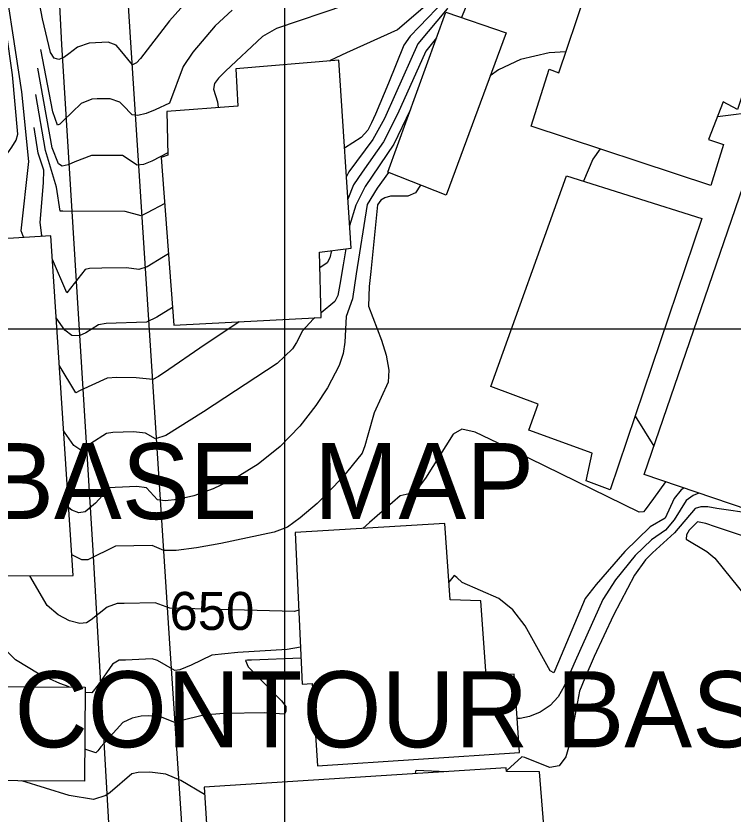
# Model space of a CAD drawing. Extents: x 79600 to 91800, y 75600 to 84400.
# Drawn here: x 85858.7 to 86236.1, y 82744.9 to 83164.7 of the extents above; entities that cross this region are included whole.
import ezdxf

# ---------------------------------------------------------------- set-up
doc = ezdxf.new("R2010")
doc.units = 0
for name, color, linetype in [('084-085$0$TI_ORTHO_BM', 7, 'Continuous'), ('084-085$0$TI_ORTHO_CBM', 7, 'Continuous'), ('084-090$0$BLDG', 7, 'Continuous'), ('084-090$0$GRID', 7, 'Continuous'), ('084-090$0$INDEX', 7, 'Continuous'), ('084-090$0$INDXLBL', 7, 'Continuous'), ('084-090$0$INTER', 7, 'Continuous'), ('084-090$0$ROAD', 7, 'Continuous')]:
    doc.layers.add(name, color=color, linetype=linetype)

msp = doc.modelspace()

# ---------------------------------------------------------------- linework, layer by layer
at = {"layer": '084-090$0$BLDG'}
for points in [[(86224.34, 83075.53), (86129.86, 83106.71), (86139.29, 83136.6), (86144.4, 83134.8), (86185.95, 83257.94), (86257.98, 83232.87), (86252.75, 83215.38), (86269.8, 83209.06), (86238.46, 83115.5), (86230.85, 83119.44), (86223.17, 83099.76), (86231.07, 83097.06)], [(86271.35, 82895.67), (86189.25, 82923.42), (86271.34, 83162.45), (86259.26, 83166.5), (86274.11, 83210.03), (86365.03, 83179.9)], [(86054.44, 83082.5), (86084.95, 83166.63), (86116.71, 83155.83), (86085.13, 83070.45)], [(85935.18, 83090.27), (85941.77, 83002.03), (86019.38, 83006.04), (86018.43, 83040.46), (86035.08, 83042.47), (86028.7, 83141.37), (85974.4, 83136.82), (85975.52, 83117.23), (85938.19, 83114.39), (85938.72, 83091.39)], [(86148.49, 83080.49), (86219.57, 83058.19), (86171.42, 82915.37), (86158.87, 82920.19), (86161.97, 82934.73), (86128.66, 82946.75), (86133.46, 82960.54), (86108.67, 82969.71)], [(85888.88, 82870.28), (85877.08, 83048.94), (85834.65, 83046.36), (85835.88, 82984.31), (85811.03, 82983.75), (85811.47, 82970.17), (85802.36, 82970.08), (85801.56, 82988.45), (85761.59, 82987.28), (85735.2, 83001.22), (85667.5, 82869.48)], [(86087.24, 82857.57), (86084.37, 82897.68), (86005.68, 82893.05), (86009.4, 82813.26), (86014.65, 82813.47), (86017.39, 82770.27), (86123.69, 82777.19), (86120.97, 82818.38), (86106.16, 82817.62), (86103.3, 82857.11)], [(85895.12, 82811.7), (85894.84, 82762.15), (85719.62, 82763.12), (85719.9, 82812.68)], [(85957.75, 82759.03), (85963.05, 82676.17), (86070.75, 82682.95), (86071.39, 82680.02), (86081.89, 82679.66), (86084.04, 82650.04), (86099.94, 82650.05), (86098.36, 82685.23), (86122.28, 82686.39), (86120.57, 82718.03), (86138.16, 82719.12), (86134.29, 82767.1), (86116.85, 82767.24), (86116.67, 82769.24)]]:
    msp.add_lwpolyline(points, close=True, dxfattribs=at)
at = {"layer": '084-090$0$GRID'}
for p, q in [((86000, 84000), (86000, 80000)), ((90000, 83000), (85000, 83000))]:
    msp.add_line(p, q, dxfattribs=at)
at = {"layer": '084-090$0$INDEX'}
msp.add_line((86184.51, 82954.18), (86194.39, 82938.38), dxfattribs=at)
for points in [[(85862.91, 83048.08), (85862.45, 83048.8), (85861.47, 83051.63), (85865.56, 83088.04), (85861.91, 83124.82), (85850.49, 83199.61), (85847.19, 83227.14), (85846.11, 83237.85), (85846.13, 83243.79), (85847.29, 83252.3), (85853.54, 83269.76), (85855.43, 83279.06), (85857.03, 83295.86)], [(86185.74, 83257.33), (86179.65, 83255.74), (86135.32, 83250.43), (86131.34, 83249.64), (86125.16, 83241.02), (86118.72, 83230.33), (86112.78, 83216.12), (86097.23, 83191.67), (86085.56, 83168.46), (86070.22, 83150.05), (86058.41, 83123.76), (86052.69, 83110.68), (86046.58, 83099.69), (86033.94, 83082.63), (86032.64, 83080.28)], [(85960.63, 83185.74), (85939.62, 83162.11), (85924.25, 83142.28), (85922.22, 83139.93), (85919.98, 83139.02), (85913.59, 83146.89), (85911.46, 83149.25), (85907.28, 83150.94), (85897.34, 83150.36), (85891.16, 83148.3), (85886.62, 83144.69), (85883.99, 83142.82), (85881.24, 83141.79), (85878.78, 83142.48), (85876.89, 83145.53), (85872.72, 83163.17), (85869.32, 83180.76)], [(86255.19, 83115.42), (86250.25, 83114.38), (86227.82, 83111.66)], [(86166.23, 83094.7), (86162.37, 83089.3), (86157.35, 83077.71)], [(85941.07, 83011.37), (85932.84, 83006.31), (85927.38, 83003.69), (85906.16, 83002.84), (85902.24, 83002.28), (85895.54, 82998), (85891.94, 82996.43), (85888.09, 82996.63), (85884.41, 82999.44), (85879.92, 83005.83)], [(86200.61, 82919.58), (86194.17, 82910.89), (86189.77, 82904.85), (86188.96, 82903.81), (86186.65, 82903.74), (86112.5, 82939.93), (86100.31, 82945.77), (86093.41, 82947.4), (86088.76, 82944.7), (86074.21, 82921.59), (86070.38, 82916.41), (86067.3, 82913.67), (86060.94, 82912.33), (86044.78, 82898.2), (86041.28, 82895.14)], [(86007.59, 82852.07), (86005.28, 82851.38), (85939.75, 82853.14), (85931.93, 82855.9), (85915.6, 82855.58), (85911.91, 82855.65), (85906.77, 82853.61), (85898.25, 82847.08), (85895.82, 82845.5), (85892.28, 82845.15), (85887, 82846.54), (85880.9, 82849.7), (85875.25, 82854.58), (85865.96, 82870.19)]]:
    msp.add_lwpolyline(points, dxfattribs=at)
at = {"layer": '084-090$0$INTER'}
for points in [[(85849.74, 83047.28), (85847.28, 83049.36), (85845.44, 83053.99), (85845.41, 83061.35), (85848.18, 83077.64), (85850.17, 83086.18), (85854.05, 83092.16), (85856.49, 83095.57), (85858.81, 83099.26), (85859.7, 83102.5), (85857, 83133.68), (85847.05, 83201.84), (85842.59, 83233.97), (85842.03, 83240.38), (85842.77, 83250.25), (85844.07, 83257.24), (85847.23, 83264.53), (85853.51, 83286.9), (85856.07, 83298.42)], [(86160.92, 83183.76), (86157.37, 83184.19), (86141.69, 83187.17), (86131.3, 83190.7), (86121.5, 83197.06), (86118.5, 83198.76), (86114.24, 83199.67), (86112.05, 83198.53), (86101.29, 83183.81), (86093.21, 83163.82)], [(86083.14, 83177.8), (86067.98, 83164.55), (86059.47, 83157.4), (86032.69, 83145.19), (86024.04, 83141.2), (86023.81, 83140.96)], [(86084.35, 83173.13), (86070.83, 83158.9), (86066.1, 83153.96), (86062.92, 83149.34), (86054.75, 83129.33), (86047.87, 83112.96), (86045.9, 83108.41), (86043.87, 83104.53), (86040.37, 83100.74), (86031.68, 83095.17)], [(85972.44, 83167.64), (85963.5, 83159.46), (85951.74, 83145.65), (85946.66, 83138.12), (85939.55, 83118.79), (85931.96, 83115.21), (85927.26, 83113.41), (85922.93, 83112.38), (85919.84, 83112.69), (85914.99, 83117.74), (85913.4, 83119.34), (85908.23, 83121.02), (85901.49, 83121.04), (85898.62, 83120.85), (85893.1, 83118.58), (85883.66, 83109.46), (85881.77, 83107.67), (85880.61, 83107.21), (85878.19, 83114.29), (85871.83, 83146.94)], [(86032.11, 83170.31), (85995.8, 83158.02), (85988.54, 83153.84), (85969.06, 83135.69), (85965.31, 83131.99), (85963.26, 83129.21), (85962.66, 83126.11), (85964.85, 83119.48), (85965.08, 83116.43)], [(86080.05, 83153.12), (86074.35, 83146.14), (86059.58, 83113.09), (86052.09, 83098.42), (86041, 83082.57), (86036.31, 83075.8), (86033.41, 83068.29)], [(86148.12, 83145.82), (86139.32, 83145.35), (86124.29, 83141.77), (86112.71, 83136.34), (86108.31, 83133.1)], [(85938.69, 83092.71), (85930.29, 83088.32), (85925.81, 83086.55), (85922.54, 83086.26), (85914.77, 83091.35), (85898.48, 83091.19), (85889.65, 83087.97), (85886.18, 83086.31), (85883.11, 83085.73), (85881.12, 83086.89), (85877.88, 83095.3), (85870.31, 83137.21)], [(85937, 83065.97), (85927.87, 83061.15), (85924.58, 83059.51), (85916.22, 83061.79), (85883.32, 83061.95), (85881.99, 83061.93), (85880.1, 83074.56), (85874.23, 83093.83), (85869.22, 83123.37)], [(86066.26, 83115.08), (86057.6, 83097.16), (86042.52, 83074.92), (86037.64, 83065.08), (86034.32, 83054.23)], [(85872.64, 83048.67), (85872.37, 83049.27), (85871.53, 83056.04), (85873.32, 83076.91), (85873.48, 83083.56), (85870.46, 83092.52), (85868.33, 83105.97)], [(86054.75, 83082.38), (86048.74, 83074.04), (86043.61, 83065.54), (86037.73, 83029.11), (86035.81, 83015.95), (86032.46, 83006.61), (86031.86, 82993.01), (86030.92, 82987.1), (86028.78, 82980.77), (86022.72, 82969.14), (86016.48, 82959.7), (86008.06, 82948.86), (85997.84, 82938.17), (85986.28, 82928.93), (85974.22, 82921.49), (85962.6, 82915.92), (85952.28, 82912.24), (85943.72, 82910.25), (85937.3, 82909.65), (85933.22, 82910.15), (85927.49, 82916.44), (85922.42, 82917.11), (85911.03, 82916.67), (85907.97, 82916.46), (85900.6, 82908.44), (85895.1, 82903.88), (85891.74, 82903.28), (85888.09, 82904.69), (85886.52, 82905.95)], [(86071.69, 83075.72), (86069.02, 83071.61), (86064.88, 83069.83), (86055.86, 83069.81), (86052.77, 83069.06), (86050.8, 83067.71), (86049.02, 83065.28), (86045.49, 83030.25), (86044.63, 83022.31), (86044.32, 83012.08), (86051.09, 82994.18), (86053.52, 82986.18), (86054.89, 82978.37), (86054.61, 82971.96), (86047.29, 82955.98), (86043.83, 82944.08), (86042.26, 82938.47), (86040.99, 82934.76), (86030.36, 82921.8), (86017.2, 82908.21), (86008.3, 82900.66), (86001.67, 82895.78), (85994.61, 82893.09), (85966.55, 82887.11), (85953.69, 82884.9), (85942.99, 82883.52), (85936.5, 82883.42), (85930.49, 82886.19), (85911.13, 82885.78), (85896.63, 82878.63), (85893.32, 82878.51), (85888.16, 82881.21)], [(86032.34, 83042.14), (86030.98, 83033.68), (86029.15, 83023.45), (86028.11, 83017.71), (86026.54, 83014.4), (86019.31, 83008.58)], [(85938.97, 83039.48), (85936.31, 83037.93), (85927.74, 83032.75), (85923.4, 83031.31), (85916.91, 83032.26), (85903.88, 83031.98), (85897.48, 83031.9), (85895.21, 83031.37), (85885.46, 83019), (85877.89, 83036.64)], [(86024.84, 83041.23), (86023.87, 83037.39), (86022.48, 83034.74), (86018.66, 83032.19)], [(85976.18, 83003.81), (85955.42, 82989.93), (85939.19, 82978.68), (85933.78, 82975.09), (85930.7, 82973.43), (85922.07, 82974.36), (85911.87, 82974.51), (85906.78, 82974.11), (85892.6, 82967.64), (85890.31, 82966.39), (85881.56, 82981.05)], [(86015.94, 83005.86), (86015.15, 83005.22), (86009.46, 82999.05), (86006.31, 82992.86), (86004.31, 82989.6), (85996.26, 82981.88), (85957.36, 82956.45), (85937.54, 82943.93), (85932.21, 82942.18), (85926.89, 82945.21), (85920.63, 82945.85), (85909.71, 82945.49), (85906.43, 82945.04), (85898.18, 82939.85), (85895.72, 82937.38), (85892.87, 82936.3), (85889.14, 82938.7), (85884.3, 82945.82), (85883.82, 82946.81)], [(86210.1, 82916.37), (86208.79, 82915.39), (86205.03, 82910.78), (86200.43, 82900.5), (86192.41, 82895.9), (86179.08, 82883.01), (86164.08, 82865.61), (86158.3, 82858.22), (86144.16, 82824.88), (86141.78, 82819.18), (86139.89, 82820.2), (86126.68, 82843.79), (86120.13, 82852.25), (86112.89, 82858.3), (86093.62, 82866.75), (86090.68, 82869.34), (86089.26, 82870.29), (86086.58, 82866.78)], [(86217.99, 82913.71), (86215.15, 82912.44), (86211.46, 82909.74), (86205.03, 82899.69), (86200.46, 82894.15), (86193.09, 82889.08), (86184.59, 82880.82), (86174.19, 82868.06), (86167.63, 82857.75), (86153.02, 82825.26), (86147.28, 82812.21), (86144.02, 82806.57), (86139.88, 82801.91), (86134.62, 82798.47), (86129.02, 82796.21), (86124.08, 82795.09), (86122.51, 82795.05)], [(86250.57, 82902.69), (86247.05, 82902.75), (86227.47, 82905.67), (86222.85, 82906.52), (86219.1, 82906.45), (86216.22, 82905.55), (86205.29, 82892.84), (86193.76, 82882.26), (86190.09, 82878.64), (86184.29, 82870.51), (86173.1, 82849.52), (86163.02, 82827.83), (86158.05, 82816.38), (86155.23, 82809.52), (86151.52, 82789.9), (86150.23, 82782.25), (86148.09, 82774.99), (86144.63, 82770.23), (86139.66, 82769.39), (86129.45, 82773.43), (86126.48, 82774.69), (86124.92, 82774.93), (86117.13, 82767.78), (86116.82, 82767.53)], [(86241, 82891.26), (86226.77, 82895.97), (86221.71, 82897.66), (86217.29, 82898.66), (86213.03, 82894.16), (86211.51, 82891.76), (86211.49, 82889.39), (86222.25, 82882.89), (86226.57, 82879.52), (86255.78, 82843.15)], [(85886.75, 82811.75), (85881.91, 82813.62), (85871.01, 82818.49), (85858.57, 82826.06), (85846.91, 82837.28), (85837.79, 82852.4), (85830.76, 82870.07)], [(86008.49, 82832.73), (86001.52, 82831.46), (85975.57, 82829.89), (85961.84, 82828.44), (85950.87, 82823.22), (85944.9, 82820.72), (85942.33, 82820.35), (85933.21, 82825.73), (85930.48, 82826.51), (85916.35, 82825.81), (85913.09, 82825.77), (85909.51, 82823.73), (85902.08, 82812.88), (85898.69, 82808.55), (85895.1, 82808.81)], [(86008.77, 82826.84), (85982.72, 82825.86), (85980.6, 82825.8), (85979.56, 82825.7), (85980.98, 82822.37), (85998.54, 82804.46), (86000.77, 82801.44), (86000.74, 82799.03), (86000.06, 82797.44), (85989.72, 82798.19), (85968.17, 82797.77), (85957.39, 82796.87), (85945.34, 82793.93), (85942.34, 82793.03), (85933.93, 82796.29), (85928.43, 82796.55), (85924.64, 82796.29), (85919.92, 82795.32), (85914.93, 82792.97), (85903.38, 82780.3), (85901.75, 82778.07), (85900.85, 82777.08), (85894.94, 82779.07)], [(85958.01, 82755.11), (85945.46, 82762.47), (85937.62, 82765.84), (85929.21, 82766.95), (85923.01, 82766.66), (85919.73, 82766.03), (85908.27, 82756.29), (85906.02, 82754.57), (85899.58, 82752.46), (85886.78, 82754.69), (85861.89, 82762.33)], [(86069, 82766.18), (86069.29, 82767.99), (86085.44, 82767.23)]]:
    msp.add_lwpolyline(points, dxfattribs=at)
at = {"layer": '084-090$0$ROAD'}
for points in [[(85854.37, 82644.22), (85870.07, 82648.7), (85882.23, 82652.68), (85891.15, 82655.7), (85901, 82659.04), (85904.84, 82660.93), (85909.29, 82664.22), (85910.94, 82668.4), (85911.33, 82676.28), (85899.4, 82883.5), (85882.87, 83149.66), (85873.52, 83330.97), (85872.83, 83340.93)], [(85908.01, 83324.98), (85918.99, 83150.63), (85939.56, 82834.5), (85951.88, 82650.28), (85954.9, 82548.26), (85956.9, 82424.15), (85955.22, 82265.27), (85956.39, 82256.48), (85958.59, 82252.65), (85963.42, 82248.37), (85971.14, 82247.83), (86290.72, 82253.44)]]:
    msp.add_lwpolyline(points, dxfattribs=at)

# ---------------------------------------------------------------- texts
at = {"layer": '084-085$0$TI_ORTHO_BM'}
msp.add_text('ORTHOPHOTO  BASE  MAP', height=40, dxfattribs=at).set_placement((85430, 82900))
at = {"layer": '084-085$0$TI_ORTHO_CBM'}
msp.add_text('ORTHOPHOTO / CONTOUR BASE MAP', height=40, dxfattribs=at).set_placement((85430, 82780))
at = {"layer": '084-090$0$INDXLBL'}
msp.add_text('650', height=20, dxfattribs=at).set_placement((85939.54, 82841.72))

doc.saveas('drawing.dxf')
